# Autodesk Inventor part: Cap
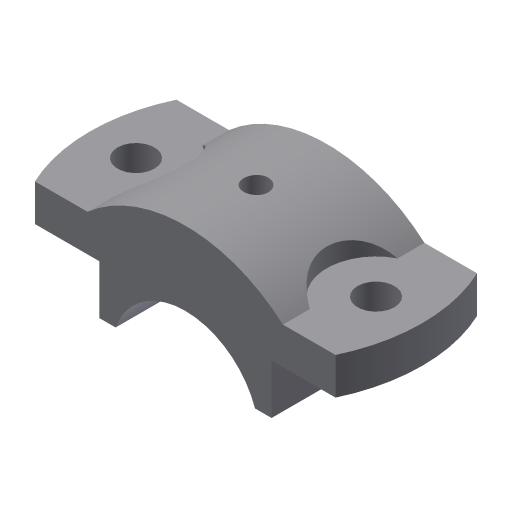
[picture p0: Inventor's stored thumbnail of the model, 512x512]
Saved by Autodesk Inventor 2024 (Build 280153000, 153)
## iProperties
Created: 2009-04
Part Number: Cap
Document SubType Name: Modeling
Designer: Sham
Density: 1 g/cm^3
Material: Generic
Appearance: Default
Mass: 94.0132 g
Surface Area: 184.419 cm^2
Volume: 94.0132 cm^3
Author: Sham
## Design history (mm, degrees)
sketch "Sketch1"
  geometry: L1 (-48.857, 23)-(48.857, 23); L2 (48.857, -23)-(-48.857, -23); A1 r 54 centre (0, 0) between (-48.857, 23) and (-48.857, -23); A2 r 54 centre (0, 0) between (48.857, -23) and (48.857, 23); 1 further point
  constraints: 4 end point, 4 point on circle, 2 centre point, 2 coincident, 1 horizontal, 1 parallel, 1 other
  dimensions: "d3" = 54 radius of A1; "d4" = 54 radius of A2; "d5" = 46 distance between parallel lines of L2 L1; "d6" = 23 distance from line of point (0, 0) L1
extrude "Extrusion1" new body sketch "Sketch1" distance "d7" = 12; taper "d8" = 0 deg
sketch "Sketch3"
  geometry: L1 (20.906, 0)-(20.906, -16); L2 (76.906, -0.137)-(76.906, -16.137); L3 (20.906, -16)-(26.23, -16); L4 (71.532, -16.137)-(76.906, -16.137); L5 (76.906, -0.137)-(76.857, 12); L6 (97.714, 0)-(0, 0) reference; L7 (76.857, 12)-(80.606, 12); L8 (17.108, 12)-(20.906, 12); L9 (20.906, 12)-(20.906, 0); L10 (0, 12)-(97.714, 12) reference; A1 r 24 centre (48.857, -24) between (71.532, -16.137) and (26.23, -16); A2 r 48 centre (48.857, -24) between (80.606, 12) and (17.108, 12); 3 further points
  constraints: 16 end point, 4 point on circle, 3 parallel, 3 perpendicular, 2 centre point, 2 coincident, 2 vertical alignment, 1 collinear, 1 midpoint, 1 vertical, 2 other
  dimensions: "d17" = 48 diameter of A1; "d18" = 16 distance of L1.start L1.end; "d19" = 56 distance between parallel lines of L2 L1; "d21" = 8 vertical distance of A1.centre L1.end; "d22" = 48 radius of A2; "d23" = 0 distance from line of L6 L1.start; "d38" = 31.74902 distance of L7.end point (48.857, 12); "d39" = 28 distance from line of point (48.857, 12) L5
extrude "Extrusion2" join sketch "Sketch3" stored distance "d24" = 12; taper "d25" = 0 deg
sketch "Sketch4"
  geometry: 2 further points
  dimensions: "d26" = 78 distance of point (39, 0) point (-39, 0)
hole "Hole1" sketch "Sketch4" at (-39, 0), (39, 0) diameter "d28" = 12; stored, may be unused: countersink angle "d32" = 90 deg, drill point angle "d34" = 118 deg; dims "d29" = 6, "d30" = 4, "d31" = 2, "d33" = 8
sketch "Sketch5"
  geometry: L1 (-31.749, -23)-(-31.749, 23) reference; L2 (-31.749, 14.263)-(-31.749, -14.263); C1 r 6 at (-39, 0) reference; A1 r 16 centre (-39, 0) between (-31.749, -14.263) and (-31.749, 14.263)
  constraints: 2 end point, 2 point on circle, 1 centre point, 1 coincident, 1 collinear, 1 point on line
  dimensions: "d35" = 16 radius of A1
extrude "Extrusion3" cut sketch "Sketch5" distance "d36" = 12; taper "d37" = 0 deg
mirror "Mirror2"
workplane "Work Plane4"
sketch "Sketch6"
  geometry: L1 (-31.749, 0)-(31.749, 0) reference; 1 further point
  dimensions: "d40" = 23 distance from line of L1 point (0, 23)
hole "Hole2" sketch "Sketch6" at (0, 23) diameter "d41" = 6; stored, may be unused: countersink angle "d45" = 90 deg, drill point angle "d47" = 118 deg; dims "d42" = 6, "d43" = 8, "d44" = 16, "d46" = 8
body "Solid1"
